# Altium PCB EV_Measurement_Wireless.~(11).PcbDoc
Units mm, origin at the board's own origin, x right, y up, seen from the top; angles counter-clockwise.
Board outline 152.4 x 101.6 mm, 4 copper layers (Top Layer, Mid-Layer 1, Mid_Layer 2, Bottom Layer), stack 0.605 mm thick; 55 components, 38 nets, 375 pads, 56 vias.
Unrouted connection lines stored in the file: 220.
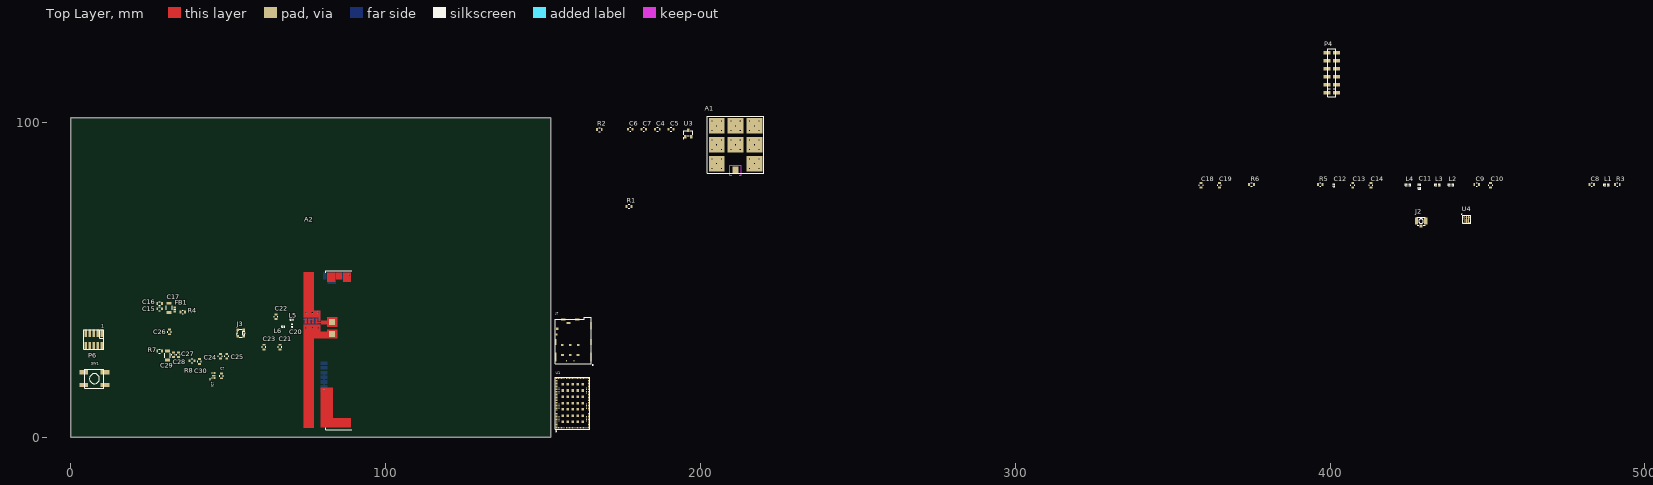
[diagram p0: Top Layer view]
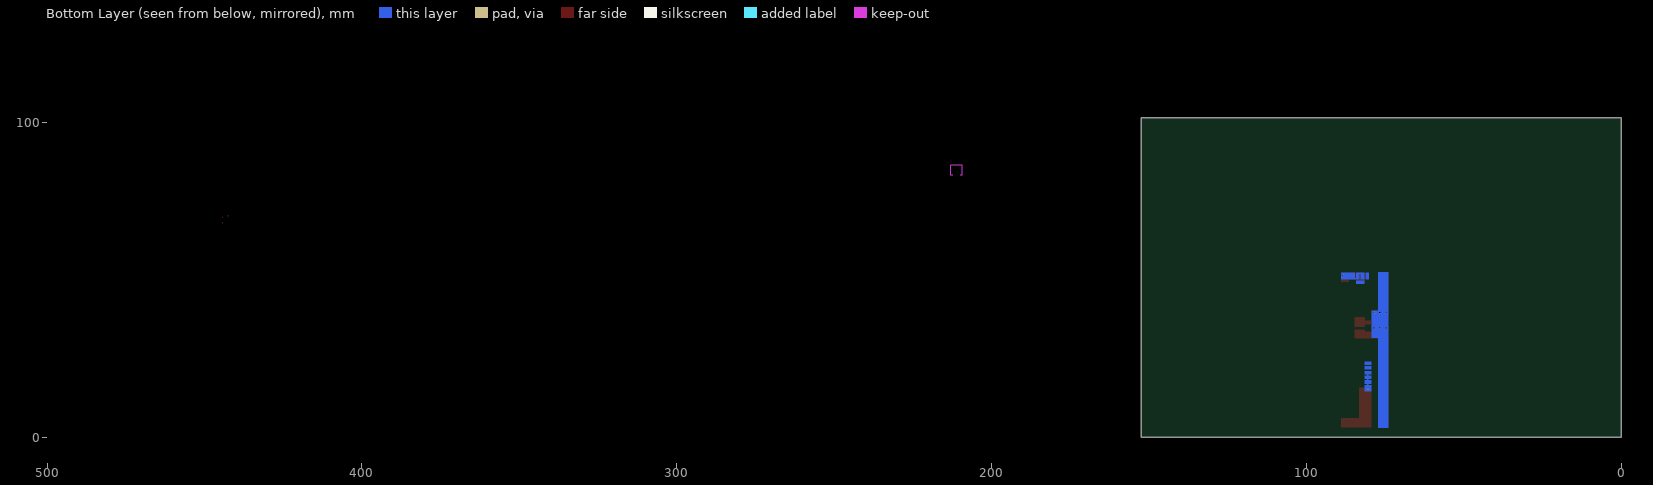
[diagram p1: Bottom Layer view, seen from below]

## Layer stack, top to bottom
Top Solder: solder mask 0.0102, Solder Resist, Dk 3.5
Top Layer: signal copper 0.0356
Dielectric 2: prepreg 0.0711, PP-006, Dk 4.1
Mid-Layer 1: signal copper 0.0356
Dielectric 1: prepreg 0.0711, PP-006, Dk 4.1
Mid_Layer 2: signal copper 0.0356
Dielectric2: dielectric 0.32, FR-4, Dk 4.1
Bottom Layer: signal copper 0.0356
Bottom Solder: solder mask 0.0102, Solder Resist, Dk 3.5

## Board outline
0,0 152.4,0 152.4,101.6 0,101.6

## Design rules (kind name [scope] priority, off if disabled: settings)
Clearance [All] p1: gap=0.254 ignorepadtopadclearanceinfootprint=FALSE
PolygonConnect [All] p1: connectstyle=Relief reliefconductorwidth=0.254 reliefentries=4 polygonreliefangle="90 Angle" airgapwidth=0.254
RoutingVias [All] p1: holewidth=0.711 width=1.27 viastyle="Through Hole" minholewidth=0.711 minwidth=1.27 maxholewidth=0.711 maxwidth=1.27
SolderMaskExpansion [All] p1: expansion=0.102 istentingtop=FALSE
SupplyNets "Schematic Supply Nets" [InNet('P0.14/AIN1')] p1: voltage=0.000
SupplyNets "Schematic Supply Nets_4" [InNet('3V3')] p2: voltage=0.000
SupplyNets "Schematic Supply Nets_3" [InNet('VDD')] p3: voltage=0.000
SupplyNets "Schematic Supply Nets_2" [InNet('VDD_nRF')] p4: voltage=0.000
Width [All] p1: maxlimit=0.254 minlimit=0.254 preferedwidth=0.254
30 further rules are at their usual default settings.

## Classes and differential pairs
net class SWD: RESET SWDCLK SWDIO
component class sheet4_sim_connections: C4 C5 C6 C7 C? IC? J? P4 P6 R1 U3
component class sheet2_nRF9160: A1 A2 C8 C9 C10 C11 C12 C13 C14 C15 C16 C17 C18 C19 C20 C21 C22 C23 C24 C25 C26 C27 C28 C29 C30 FB1 J2 J3 L1 L2 L3 L4 L5 L6 R2 R3 R4 R5 R6 R7 R8 SW1 U1 U4

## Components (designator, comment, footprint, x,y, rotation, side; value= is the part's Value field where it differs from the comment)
A1 "DSGP.1575.18" DSGP.1575.18 211.129,92.988 r0 top
A2 "P822601" P822601 85.217,27.813 r270 top
C4 "100n" 0603(1608)C 186.309,97.917 r0 top
C5 "100n" 0603(1608)C 190.627,97.917 r0 top
C6 "1u0" 0603(1608)C 177.673,97.917 r0 top
C7 "1u0" 0603(1608)C 181.991,97.917 r0 top
C8 "39p" 0603(1608)C 483.108,80.391 r0 top
C9 "39p" 0603(1608)C 446.532,80.391 r0 top
C10 "39p" 0603(1608)C 450.977,80.137 r90 top
C11 "N.C." CAPC1005X04L_NC 428.371,79.756 r90 top
C12 "N.C." CAPC0603X03L_C_NC 401.193,80.137 r90 top
C13 "100p" 0603(1608)C 407.162,80.137 r90 top
C14 "100n" 0603(1608)C 413.004,80.137 r90 top
C15 "39p" 0603(1608)C 28.194,40.894 r180 top
C16 "100n" 0603(1608)C 28.194,42.545 r180 top
C17 "47u" 1206(3216)C 31.242,41.201 r270 top
C18 "100n" 0603(1608)C 359.029,80.137 r90 top
C19 "100p" 0603(1608)C 364.871,80.137 r90 top
C20 "3.5pF" CAPC0603X03L_C 70.327,35.56 r90 top
C21 "N.C" 0603(1608)C 66.421,28.702 r90 top
C22 "N.C." 0603(1608)C 65.151,38.354 r90 top
C23 "N.C." 0603(1608)C 61.341,28.702 r90 top
C24 "100n" 0603(1608)C 47.498,25.781 r90 top
C25 "4u7" 0603(1608)C 49.53,25.781 r90 top
C26 "4u7" 0603(1608)C 31.369,33.528 r90 top
C27 "15p" 0603(1608)C 32.639,26.289 r270 top value=39p
C28 "100n" 0603(1608)C 34.163,26.289 r270 top
C29 "47u" 1206(3216)C 30.734,26.035 r270 top
C30 "100n" 0603(1608)C 40.894,24.13 r90 top
C? "100n" 0603(1608)C 47.879,19.558 r270 top
FB1 "BLM18EG221SN1D" BLM18SP221SN1B 33.02,40.68 r270 top
IC? "EMIF03SIM02M8" SON40P150X170X60-9N-D 45.412,19.647 r90 top
J2 "MHF I Receptacle" "COAXIAL RF U.FL-R-SMT-1" 428.879,68.707 r0 top
J3 "MM8130-2600" COAXIAL-SWF 53.975,33.147 r90 top
J? "SF72S006VBAR2500" SF72S006VBAR2500 165.227,23.622 r0 top
L1 "68nH" INDC1005X04L_WW 487.807,80.264 r0 top
L2 "N.C." INDC1005X04L_NC 438.404,80.264 r0 top
L3 "N.C." INDC1005X04L_NC 434.086,80.264 r0 top
L4 "9.1nH" INDC1005X04L_WW 424.688,80.264 r0 top
L5 "1.5nH" INDC0603X03L_C 70.231,37.465 r0 top
L6 "22nH" INDC0603X03L_C 67.437,35.306 r0 top
P4 "Socket 1x6" SOCKET_1x6_SMD 400.499,109.474 r90 top
P6 "Pin Header 2x5, 1.27mm" HDR_2x5-SMD-1.27mm-K 7.239,31.115 r180 top
R1 "N.C" 0603(1608) 177.292,73.406 r0 top value=0E
R2 "N.C" 0603(1608) 167.894,97.79 r0 top value=0E
R3 "0E" 0603(1608) 491.236,80.391 r0 top
R4 "10k" 0603(1608) 35.56,39.878 r0 top
R5 "0E" 0603(1608) 396.875,80.391 r0 top
R6 "1M" 0603(1608) 375.031,80.391 r0 top
R7 "N.C." 0603(1608) 28.194,27.432 r0 top value=0E
R8 "1k" 0603(1608) 38.481,24.384 r0 top
SW1 "PB SW" Switch-PB-6.2x6.3mm-SMD 7.493,18.669 r0 top
U1 "nRF9160-SICAB1A" LGA50P1600X1050X104-161N 159.385,10.922 r90 top
U3 "AP7333-33SAG-7" SOT-23A 195.199,95.504 r0 top
U4 "SKY65943-11" SKY65943-11 443.357,69.342 r0 top

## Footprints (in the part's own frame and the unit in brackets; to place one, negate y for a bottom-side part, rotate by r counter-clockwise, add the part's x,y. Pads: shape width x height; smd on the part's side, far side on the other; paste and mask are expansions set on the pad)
0603(1608) [mm] "Chip 0603 (1608 metric)"
  rect 0.6x0.9 smd: 1(-0.75,0) 2(0.75,0)
  silkscreen extent -0.2,-0.6 0.2,0.6, body extent -0.8,-0.4 0.8,0.4, height 0.3
0603(1608)C [mm] "Chip 0603 (1608 metric)"
  rect 0.6x0.9 smd: 1(-0.75,0) 2(0.75,0)
  silkscreen extent -0.2,-0.6 0.2,0.6, body extent -0.8,-0.38 0.8,0.42, height 0.5
1206(3216)C [mm] "Chip Capa 1206 (3216 metric)"
  rect 0.9x1.6 smd: 1(-1.45,0) 2(1.45,0)
  silkscreen extent -0.7,-0.9 0.7,0.9, body extent -1.6,-0.8 1.6,0.8, height 1
BLM18SP221SN1B [mm]
  rect 0.65x0.7 smd: 1(-0.675,0) 2(0.675,0)
  silkscreen extent 0,-0.3 0,0.3, body extent -0.8,-0.4 0.8,0.4, height 0.8
CAPC0603X03L_C [mm]
  rect 0.27x0.3 smd mask+0.05: 1(-0.285,0) 2(0.285,0)
  silkscreen extent -0.49,-0.22 0.49,0.22, body extent -0.3,-0.15 0.31,0.15, height 0.3
CAPC0603X03L_C_NC [mm]
  rect 0.27x0.3 smd mask+0.05: 1(-0.285,0) 2(0.285,0)
  silkscreen extent -0.49,-0.22 0.49,0.22
CAPC1005X04L_NC [mm]
  rect 0.6x0.5 smd: 1(-0.5,0) 2(0.5,0)
  silkscreen extent -0.9,-0.35 0.9,0.35
"COAXIAL RF U.FL-R-SMT-1" [mm]
  rect 1x1.05 smd: 1(0,-1.525)
  rect 1.05x2.2 smd: 2(-1.475,0) 2(1.475,0)
  Top Layer pour cut-out: 0.85,1.3 -0.85,1.3 -0.85,-1.525 0.85,-1.525
  silkscreen extent -1.32,-1.3 1.28,1.3, body extent -1.5,-1.6 1.5,1.5, height 1.25
COAXIAL-SWF [mm]
  rect 0.5x0.58 smd: 1(0,1.16) 3(0,-1.16)
  rect 0.75x0.8 smd: 2(-1.025,-0.95) 2(-1.025,0.95) 2(1.025,-0.95) 2(1.025,0.95)
  Top Layer pour cut-out: -0.65,0.55 0.65,0.55 0.65,1.35 -0.65,1.35
  Top Layer pour cut-out: 0.65,-0.55 -0.65,-0.55 -0.65,-1.35 0.65,-1.35
  silkscreen extent -1.25,-1.25 1.25,1.25, body extent -1.26,-1.3 1.26,1.3, height 1.55
DSGP.1575.18 [mm]
  rect 2x2.5 smd paste-0.25 mask+0.1: 1(0,-8.1)
  rect 5x5 smd paste-0.6 mask+0.1: 2(-6,-6) 2(-6,0) 2(-6,6) 2(0,0) 2(0,6) 2(6,-6) 2(6,0) 2(6,6)
  round 0.35 on Mech16: 11(-7.5,-7.5) 11(-7.5,-4.5) 11(-7.5,-1.5) 11(-7.5,1.5) 11(-7.5,4.5) 11(-7.5,7.5) 11(-6,-6) 11(-6,0) 11(-6,6) 11(-4.5,-7.5) 11(-4.5,-4.5) 11(-4.5,-1.5) 11(-4.5,1.5) 11(-4.5,4.5) 11(-4.5,7.5) 11(-1.5,-1.5) 11(-1.5,1.5) 11(-1.5,4.5) 11(-1.5,7.5) 11(0,0) 11(0,6) 11(1.5,-1.5) 11(1.5,1.5) 11(1.5,4.5) 11(1.5,7.5) 11(4.5,-7.5) 11(4.5,-4.5) 11(4.5,-1.5) 11(4.5,1.5) 11(4.5,4.5) 11(4.5,7.5) 11(6,-6) 11(6,0) 11(6,6) 11(7.5,-7.5) 11(7.5,-4.5) 11(7.5,-1.5) 11(7.5,1.5) 11(7.5,4.5) 11(7.5,7.5)
  Keep-Out Layer lines w0.01: -1.26,-9.69 -1.84,-9.69 -1.84,-6.51 1.84,-6.51 1.84,-9.69 1.26,-9.69
  Multi-Layer pour cut-out: -2,-6.35 -2,-9.85 2,-9.85 2,-6.35
  silkscreen extent -9,-9 9,9, body extent -9,-9 9,9, height 4.03
HDR_2x5-SMD-1.27mm-K [mm]
  rect 0.76x2.4 smd: 1(-2.54,-1.95) 2(-2.54,1.95) 3(-1.27,-1.95) 4(-1.27,1.95) 5(0,-1.95) 6(0,1.95) 7(1.27,-1.95) 8(1.27,1.95) 9(2.54,-1.95) 10(2.54,1.95)
  silkscreen extent -3.18,-3.15 3.18,3.15, body extent -3.14,-2.92 3.14,2.92, height 6.11
INDC0603X03L_C [mm]
  rect 0.27x0.3 smd: 1(-0.285,0) 2(0.285,0)
  silkscreen extent -0.49,-0.22 0.49,0.22, body extent -0.31,-0.16 0.31,0.16, height 0.26
INDC1005X04L_NC [mm]
  rect 0.65x0.5 smd: 1(-0.475,0) 2(0.475,0)
  silkscreen extent -0.9,-0.35 0.9,0.35
INDC1005X04L_WW [mm]
  rect 0.65x0.5 smd: 1(-0.475,0) 2(0.475,0)
  silkscreen extent -0.9,-0.35 0.9,0.35, body extent -0.5,-0.3 0.5,0.3, height 0.51
LGA50P1600X1050X104-161N [mm]
  rect 0.54x0.54 smd mask+0.05: 1(-7.87,5.12) 21(-7.87,-5.12) 52(7.87,-5.12) 72(7.87,5.12)
  rect 0.54x0.3 smd mask+0.05: 2(-7.87,4.5) 3(-7.87,4) 4(-7.87,3.5) 5(-7.87,3) 6(-7.87,2.5) 7(-7.87,2) 8(-7.87,1.5) 9(-7.87,1) 10(-7.87,0.5) 11(-7.87,0) 12(-7.87,-0.5) 13(-7.87,-1) 14(-7.87,-1.5) 15(-7.87,-2) 16(-7.87,-2.5) 17(-7.87,-3) 18(-7.87,-3.5) 19(-7.87,-4) 20(-7.87,-4.5) 53(7.87,-4.5) 54(7.87,-4) 55(7.87,-3.5) 56(7.87,-3) 57(7.87,-2.5) 58(7.87,-2) 59(7.87,-1.5) 60(7.87,-1) 61(7.87,-0.5) 62(7.87,0) 63(7.87,0.5) 64(7.87,1) 65(7.87,1.5) 66(7.87,2) 67(7.87,2.5) 68(7.87,3) 69(7.87,3.5) 70(7.87,4) 71(7.87,4.5)
  rect 0.3x0.54 smd mask+0.05: 22(-7.25,-5.12) 23(-6.75,-5.12) 24(-6.25,-5.12) 25(-5.75,-5.12) 26(-5.25,-5.12) 27(-4.75,-5.12) 28(-4.25,-5.12) 29(-3.75,-5.12) 30(-3.25,-5.12) 31(-2.75,-5.12) 32(-2.25,-5.12) 33(-1.75,-5.12) 34(-1.25,-5.12) 35(-0.75,-5.12) 36(-0.25,-5.12) 37(0.25,-5.12) 38(0.75,-5.12) 39(1.25,-5.12) 40(1.75,-5.12) 41(2.25,-5.12) 42(2.75,-5.12) 43(3.25,-5.12) 44(3.75,-5.12) 45(4.25,-5.12) 46(4.75,-5.12) 47(5.25,-5.12) 48(5.75,-5.12) 49(6.25,-5.12) 50(6.75,-5.12) 51(7.25,-5.12) 73(7.25,5.12) 74(6.75,5.12) 75(6.25,5.12) 76(5.75,5.12) 77(5.25,5.12) 78(4.75,5.12) 79(4.25,5.12) 80(3.75,5.12) 81(3.25,5.12) 82(2.75,5.12) 83(2.25,5.12) 84(1.75,5.12) 85(1.25,5.12) 86(0.75,5.12) 87(0.25,5.12) 88(-0.25,5.12) 89(-0.75,5.12) 90(-1.25,5.12) 91(-1.75,5.12) 92(-2.25,5.12) 93(-2.75,5.12) 94(-3.25,5.12) 95(-3.75,5.12) 96(-4.25,5.12) 97(-4.75,5.12) 98(-5.25,5.12) 99(-5.75,5.12) 100(-6.25,5.12) 101(-6.75,5.12) 102(-7.25,5.12)
  rect 0.8x0.8 smd mask+0.05: 103(-6,-3.2) 103(-6,-1.6) 103(-6,0) 103(-6,1.6) 103(-6,3.2) 103(-4,-3.2) 103(-4,-1.6) 103(-4,0) 103(-4,1.6) 103(-4,3.2) 103(-2,3.2) 103(-2,-1.6) 103(-2,0) 103(-2,1.6) 103(-2,-3.2) 103(0,3.2) 103(0,1.6) 103(0,0) 103(0,-1.6) 103(0,-3.2) 103(2,3.2) 103(2,-1.6) 103(2,0) 103(2,1.6) 103(2,-3.2) 103(4,-3.2) 103(4,-1.6) 103(4,0) 103(4,1.6) 103(4,3.2) 103(6,-3.2) 103(6,-1.6) 103(6,0) 103(6,1.6) 103(6,3.2)
  rect 0.3x0.3 smd mask+0.05: 104(-5.75,-4.35) 105(-5.25,-4.35) 106(-4.75,-4.35) 107(-4.25,-4.35) 108(-1.75,-4.35) 109(-1.25,-4.35) 110(-0.75,-4.35) 111(-0.25,-4.35) 112(3.25,-4.35) 113(3.75,-4.35) 114(4.25,-4.35) 115(4.75,-4.35) 116(4.75,4.35) 117(4.25,4.35) 118(3.75,4.35) 119(3.25,4.35) 120(-0.25,4.35) 121(-0.75,4.35) 122(-1.25,4.35) 123(-1.75,4.35) 124(-4.25,4.35) 125(-4.75,4.35) 126(-5.25,4.35) 127(-5.75,4.35)
  Top Layer pour cut-out: -8.15,5.4 8.15,5.4 8.15,-5.4 -8.15,-5.4
  silkscreen extent -9.05,-5.5 8.25,5.5, body extent -8.05,-5.3 8.05,5.3, height 1.2
P822601 [mm]
  rect 2x2 smd: 1(-8.89,-2.286) 2(-5.08,-2.286)
  Top Layer region: -8.45,-8.196 -8.95,-8.196 -8.95,-7.996 -8.45,-7.996
  Top Layer region: -9.45,-8.196 -9.95,-8.196 -9.95,-7.996 -9.45,-7.996
  Top Layer region: -8.45,-8.396 -9.95,-8.396 -9.95,-8.196 -8.45,-8.196
  Top Layer region: -8.45,-8.596 -8.95,-8.596 -8.95,-8.396 -8.45,-8.396
  Top Layer region: -9.45,-8.596 -9.95,-8.596 -9.95,-8.396 -9.45,-8.396
  Top Layer region: -9.6,-9.196 -9.8,-9.196 -9.8,-8.596 -9.6,-8.596
  Top Layer region: -8.45,-9.396 -8.95,-9.396 -8.95,-9.196 -8.45,-9.196
  Top Layer region: -9.45,-9.396 -9.95,-9.396 -9.95,-9.196 -9.45,-9.196
  Top Layer region: -8.45,-9.596 -9.95,-9.596 -9.95,-9.396 -8.45,-9.396
  Top Layer region: -8.45,-9.796 -8.95,-9.796 -8.95,-9.596 -8.45,-9.596
  Top Layer region: -9.45,-9.796 -9.95,-9.796 -9.95,-9.596 -9.45,-9.596
  Top Layer region: -21.6,1.254 -24.5,1.254 -24.5,3.754 -21.6,3.754
  Top Layer region: -22.4,-0.846 -24.5,-0.846 -24.5,0.854 -22.4,0.854
  Top Layer region: -21.6,-3.746 -24.5,-3.746 -24.5,-1.246 -21.6,-1.246
  Top Layer region: 24.6,-5.796 12.05,-5.796 12.05,-2.046 24.6,-2.046
  Top Layer region: 24.6,-2.046 21.7,-2.046 21.7,3.754 24.6,3.754
  Top Layer region: -3.67,-7.991 -8.05,-7.991 -8.05,-5.996 -3.67,-5.996
  Top Layer region: -3.67,-5.996 -5.71,-5.996 -5.71,-3.826 -3.67,-3.826
  Top Layer region: -3.67,-3.826 -6.399,-3.826 -6.4,-0.566 -3.67,-0.566
  Top Layer region: -10.45,-7.996 -12.45,-7.996 -12.45,-6.496 -10.45,-6.496
  Top Layer region: -9.2,-6.496 -12.45,-6.496 -12.45,-5.996 -9.2,-5.996
  Top Layer region: -9.45,-7.496 -9.95,-7.496 -9.95,-7.296 -9.45,-7.296
  Top Layer region: -8.45,-7.496 -8.95,-7.496 -8.95,-7.296 -8.45,-7.296
  Top Layer region: -8.45,-7.296 -9.95,-7.296 -9.95,-7.096 -8.45,-7.096
  Top Layer region: -9.45,-7.096 -9.95,-7.096 -9.95,-6.896 -9.45,-6.896
  Top Layer region: -8.45,-7.096 -8.95,-7.096 -8.95,-6.896 -8.45,-6.896
  Top Layer region: -8.6,-6.896 -8.8,-6.896 -8.8,-5.696 -8.6,-5.696
  Top Layer region: -8.2,-5.696 -9.2,-5.696 -9.2,-3.796 -8.2,-3.796
  Top Layer region: -7.3,-3.796 -10.4,-3.796 -10.4,-0.596 -7.3,-0.596
  Top Layer region: -9.6,-11.296 -9.8,-11.296 -9.8,-10.896 -9.6,-10.896
  Top Layer region: -9.45,-10.896 -9.95,-10.896 -9.95,-10.696 -9.45,-10.696
  Top Layer region: -8.45,-10.896 -8.95,-10.896 -8.95,-10.696 -8.45,-10.696
  Top Layer region: -8.45,-10.696 -9.95,-10.696 -9.95,-10.496 -8.45,-10.496
  Top Layer region: -9.45,-10.496 -9.95,-10.496 -9.95,-10.296 -9.45,-10.296
  Top Layer region: -8.45,-10.496 -8.95,-10.496 -8.95,-10.296 -8.45,-10.296
  Top Layer region: 24.75,-11.296 -8.05,-11.296 -8.05,-8.001 24.75,-8.001
  Top Layer region: -10.45,-11.296 -24.65,-11.296 -24.65,-7.996 -10.45,-7.996
  Bottom Layer region: -22.5,-3.546 -24.5,-3.546 -24.5,-2.546 -22.5,-2.546
  Bottom Layer region: -24.196,-2.546 -24.5,-2.546 -24.5,-2.046 -24.196,-2.046
  Bottom Layer region: -22.5,-2.046 -24.5,-2.046 -24.5,-1.046 -22.5,-1.046
  Bottom Layer region: -22.5,-1.046 -22.8,-1.046 -22.8,-0.546 -22.5,-0.546
  Bottom Layer region: -22.5,-0.546 -24.5,-0.546 -24.5,3.754 -22.5,3.754
  Bottom Layer region: -21,-3.546 -22,-3.546 -22,-1.046 -21,-1.046
  Bottom Layer region: -22.5,-5.046 -24.5,-5.046 -24.5,-4.046 -22.5,-4.046
  Bottom Layer region: 7.7,-5.796 6.7,-5.796 6.7,-4.896 7.7,-4.896
  Bottom Layer region: 9.2,-5.796 8.2,-5.796 8.2,-4.896 9.2,-4.896
  Bottom Layer region: 10.7,-5.796 9.7,-5.796 9.7,-4.896 10.7,-4.896
  Bottom Layer region: 13.2,-5.796 11.2,-5.796 11.2,-4.896 13.2,-4.896
  Bottom Layer region: 13.2,-4.896 6.7,-4.896 6.7,-4.596 13.2,-4.596
  Bottom Layer region: 7.7,-4.596 6.7,-4.596 6.7,-3.746 7.7,-3.746
  Bottom Layer region: 9.2,-4.596 8.2,-4.596 8.2,-3.746 9.2,-3.746
  Bottom Layer region: 10.7,-4.596 9.7,-4.596 9.7,-3.746 10.7,-3.746
  Bottom Layer region: 13.2,-4.596 11.2,-4.596 11.2,-3.746 13.2,-3.746
  Bottom Layer region: 6.2,-5.796 5.2,-5.796 5.2,-3.746 6.2,-3.746
  Bottom Layer region: 4.7,-5.796 3.7,-5.796 3.7,-3.746 4.7,-3.746
  Bottom Layer region: -3.86,-7.996 -12.45,-7.996 -12.45,-5.996 -3.86,-5.996
  Bottom Layer region: 24.752,-11.296 -24.648,-11.296 -24.65,-7.996 24.75,-7.996
  Multi-Layer pour cut-out: -39.95,5.08 39.05,5.08 39.05,-7.996 -39.95,-7.996
  silkscreen extent -25.2,-4.25 25.3,4.05, body extent -24.95,-4 25.05,4, height 3.2
SF72S006VBAR2500 [mm]
  rect 0.45x2.9 smd: 0(-11.175,1.9) 0(0,1.9)
  rect 0.45x1.9 smd: 0(-11.175,6.75) 0(0,6.75)
  rect 0.75x0.7 smd: 0(-10.675,10.9)
  rect 1.4x0.5 smd: 0(-8.78,13.85) 0(-4.38,13.85)
  rect 0.3x0.6 smd: 0(-7.8,0.75) 0(-5.36,0.75)
  rect 0.45x2.4 smd: 0(0,11.9)
  rect 0.9x0.7 smd: C1(-4.14,2.6) C2(-6.58,2.6) C3(-9.02,2.6) C5(-4.04,5.77) C6(-6.58,5.77) C7(-9.12,5.77)
  rect 0.6x0.6 smd: CSW(-10.95,9.1)
  rect 1.2x0.65 smd: DSW(-7.13,12.775)
  Top Layer pour cut-out: -10.084,9.5 -3.073,9.5 -3.073,-0.025 -10.084,-0.025
  Top Layer pour cut-out: -8.407,13.106 -3.48,13.106 -3.48,9.855 -8.407,9.855
  silkscreen extent -11.3,-0.67 0.67,14.53, body extent -11.2,0.05 0.02,14.4, height 1.25
SKY65943-11 [mm]
  rect 0.425x0.515 smd mask+0.05: 1(-1.188,1.144) 5(-1.188,-1.144) 6(1.188,-1.144) 10(1.188,1.144)
  rect 0.425x0.275 smd mask+0.05: 2(-1.188,0.5) 3(-1.188,0) 4(-1.188,-0.5) 7(1.188,-0.5) 8(1.188,0) 9(1.188,0.5)
  rect 1.45x2.802 smd paste-2 mask-5: 11(0,0)
  rect 1.55x2.487 on Top Solder: ""(0,0)
  Top Layer region: -0.988,0.887 -0.713,0.887 -0.713,1.4 -0.988,1.4
  Top Layer region: 0.712,-1.4 0.987,-1.4 0.987,-0.887 0.712,-0.887
  Top Layer region: 0.712,0.363 0.987,0.363 0.987,0.637 0.712,0.637
  Top Layer region: -0.712,-0.362 -0.987,-0.362 -0.987,-0.637 -0.712,-0.637
  silkscreen extent -1.65,-1.3 1.3,1.65, body extent -1.25,-1.25 1.25,1.25, height 0.71
SOCKET_1x6_SMD [mm]
  rect 1.02x2.19 smd: 1(0,1.465) 1(0,-1.465) 2(2.54,-1.465) 2(2.54,1.465) 3(5.08,-1.465) 3(5.08,1.465) 4(7.62,-1.465) 4(7.62,1.465) 5(10.16,-1.465) 5(10.16,1.465) 6(12.7,1.465) 6(12.7,-1.465)
  silkscreen extent -1.27,-1.27 13.97,1.27, body extent -1.27,-2.29 13.97,2.29, height 7.47
SON40P150X170X60-9N-D [mm]
  rect 0.7x0.2 smd: 1(-0.8,0.6) 2(-0.8,0.2) 3(-0.8,-0.2) 4(-0.8,-0.6) 5(0.8,-0.6) 6(0.8,-0.2) 7(0.8,0.2) 8(0.8,0.6)
  rect 0.5x1.1 smd: 9(0,0)
  silkscreen extent -1.27,1.07 -1.03,1.32, body extent -0.8,-0.85 0.8,0.85, height 0.6
SOT-23A [mil]
  rect 30x40 smd: 1(0,0) 2(74.8,0) 3(37.4,82.68)
  silkscreen extent -27,-21 94,79, body extent -20,-5 95,87, height 39
Switch-PB-6.2x6.3mm-SMD [mm]
  rect 2.75x1.4 smd: 1(-3.375,2) 1(3.375,2) 2(-3.375,-2) 2(3.375,-2)
  silkscreen extent -3,-3 3,3, body extent -4,-3 4,3.3, height 3.1

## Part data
A1: library part DSGP.1575.18.4.A.02, "18 x 18 mm Low Profile GPS L1 / GALILEO E1 Passive Patch Antenna", Manufacturer=Taoglas, Part number IPS=00000004435, Part number Norautron=N.A., Supplier Part Number 1=931-1511-1-ND
A2: "ANTENNA PRESTTA OCTABAND LTE", Manufacturer=Ethertronics, Part number IPS=00000009001, Part number Norautron=N.A.
C4 C5 C14 C16 C18 C24 C28 C30 C?: library part C0603_5_100n_25V, "Cer Chip Capacitor / 100n/ +-5%/ 25V", Capacitance=100nF, Case Code (Imperial)=0603, Case Code (Metric)=1608, Dielectric=X7R, Manufacturer 1=Yageo, Manufacturer Part Number=CC0603KRX7R8BB104, Max Operating Temperature=125°C, Min Operating Temperature=-55°C, Package Quantity=1, Special Value 1=+-5%, Special Value 2=25V, Supplier Part Number 1=311-1341-1-ND, Tolerance=10%
C6 C7: library part C0603_6_1u0_25V, "Cer Chip Capacitor / 1u0 / +-10%/ 25V", Capacitance=1uF, Case Code (Imperial)=0603, Case Code (Metric)=1608, Manufacturer 1=Samsung, Manufacturer Part Number=CL10B105KA8VPNC, Max Operating Temperature=125°C, Min Operating Temperature=-55°C, Special Value 1=+-10%, Special Value 2=25V, Supplier Part Number 1=1276-6617-1-ND, Tolerance=10%
C8 C9 C10: library part C0603_1_39p_50V, "Cer Chip Capacitor / 39p/ +-1%/ 50V", Manufacturer=Murata, Manufacturer P/N=GCM1885C1H390FA16J, Special Value 1=+-1%, Special Value 2=50V
C11: library part C0402-N.C., "Not mounted", Manufacturer=N.A.
C12: library part C0201-N.C., "Not mounted", Manufacturer=N.A.
C13 C19: library part C0603_2_100p_50V, "Cer Chip Capacitor / 100p/ +-1%/ 50V", Manufacturer=Murata, Manufacturer P/N=GCM1885C1H101FA16D, Special Value 1=+-1%, Special Value 2=50V
C15 C27: library part C0603_1_39p_50V, "Cer Chip Capacitor / 15p/ +-1%/ 50V", Manufacturer=Murata, Manufacturer P/N=GCM1885C1H390FA16J, Special Value 1=+-1%, Special Value 2=50V
C17 C29: library part C1206_7_47u_6.3V, "Cer Chip Capacitor / 47u/ +-10%/ 6.3V", Capacitance=47uF, Case Code (Imperial)=1206, Case Code (Metric)=3216, Dielectric=X5R, Manufacturer 1=Samsung, Manufacturer Part Number=CL31A476MQHNNNE, Max Operating Temperature=85°C, Min Operating Temperature=-55°C, Package Quantity=1, Special Value 1=+-20%, Special Value 2=6.3V, Supplier Part Number 1=1276-1167-1-ND, Tolerance=20%
C20: library part C0201-3.5p, "Capacitor, NP0, ±0.1pF, 25V", Manufacturer=Murata, Manufacturer Part Number=GJM0335C1H3R5BB01E, Part number IPS=00000001469, Part number Norautron=N.A.
C21 C22 C23: library part C0603, "Cer Chip Capacitor"
C25 C26: library part C0603_6_4u7_25V, "Cer Chip Capacitor / 4u7/ +-10%/ 25V", Capacitance=4.7uF, Case Code (Imperial)=0603, Case Code (Metric)=1608, Dielectric=X5R, Manufacturer 1=Samsung, Manufacturer Part Number=CL10A475MA8NQNC, Max Operating Temperature=85°C, Min Operating Temperature=-55°C, Package Quantity=1, Special Value 1=+-10%, Special Value 2=25V, Supplier Part Number 1=1276-1903-1-ND, Tolerance=20%
FB1: "Ferrite Bead", Manufacturer_Name="Murata Electronics", Mouser Part Number=81-BLM18EG221SN1D
IC?: "Integrated Circuit", Manufacturer_Name=STMicroelectronics
J2: library part 20279-001E-03, "Ultraminiature Coaxial Connector, 50 Ohm, SMD", Manufacturer=Wellshow, Part number IPS=00000004436, Part number Norautron=N.A.
J3: "Coaxial Connector with Switch", Manufacturer=Murata, Part number IPS=00000009955, Part number Norautron=N.A., Supplier Part Number 1=490-4981-1-ND
J?: "n 8 (6 + 2) Position Card Connector NANO SIM Surface Mount, Right Angle Gold", Manufacturer="JAE Electronics", Part number IPS=00000009956, Part number Norautron=N.A., Supplier Part Number 1=670-2799-1-ND
L1: library part L0402-68n-Wirewound-Murata, "Inductor, 140mA, ±2%, 1960mΩ, Q=20", Manufacturer=Murata, Manufacturer Part Number=LQW15AN68NG00, Part number IPS=00000002494, Part number Norautron=N.A., Supplier Part Number 1=490-6837-1-ND
L2 L3: library part L0402-N.C., "Not mounted", Manufacturer=N.A.
L4: library part L0402-9n1-Wirewound-Murata, "Inductor, 540mA, ±2%, 140mΩ, Q=25", Manufacturer=Murata, Manufacturer Part Number=LQW15AN9N1G00, Part number IPS=00000002497, Part number Norautron=N.A., Supplier Part Number 1=490-6854-1-ND
L5: library part L0201-1n5, "Inductor, 650mA, ±0.1nH", Manufacturer=Murata, Manufacturer Part Number=LQP03TQ1N5B02D, Part number IPS=00000000836, Part number Norautron=N.A.
L6: library part L0201-22n, "Chip Inductor", Manufacturer=N.A., Part number IPS=00000001478
P4: library part "Socket 1x6 SMD", "Socket 1x6, 2.54mm (100mil), SMD", Manufacturer=W-CON, Manufacturer Part Number=2171-106MS0CUNR1, Part number IPS=00000009964, Part number Norautron=N.A.
P6: library part "Pin Header 2x5 SMD, 1.27mm, KS", "Pin Header 2x5, 1.27mm (50mil), SMD, Keying Shroud", Manufacturer=W-CON, Manufacturer Part Number=3132-10MS0BK00R1, Part number IPS=00000009968, Part number Norautron=N.A.
R1 R2 R3 R5 R7: library part R0603_0_0E, "Chip Resistor / 0E / 1% / 50V / 100mW / 0603(1608)", Case Code (Imperial)=0603, Case Code (Metric)=1608, Manufacturer 1=Panasonic, Manufacturer Part Number=ERJ-3GEY0R00V, Max Operating Temperature=155°C, Max Power Dissipation=100mW, Min Operating Temperature=-55°C, Package Quantity=1, Resistance=0mR, Special Value 1=1%, Special Value 2=50V, Supplier Part Number 1=311-0.0HRCT-ND, Temperature Coefficient=600ppm/°C, Tolerance=0%, Voltage Rating=75V
R4: library part R0603_4_10k, "Chip Resistor / 10k/ 1% / 50V / 100mW / 0603(1608)", Case Code (Imperial)=0603, Case Code (Metric)=1608, Manufacturer 1=Susumu, Manufacturer Part Number=RR0816P-103-D, Max Operating Temperature=125°C, Max Power Dissipation=63mW, Min Operating Temperature=-55°C, Package Quantity=1, Resistance=10kR, Special Value 1=1%, Special Value 2=50V, Special Value 3=100mW, Supplier Part Number 1=RR08P10.0KDCT-ND, Temperature Coefficient=25ppm/°C, Tolerance=0.5%, Voltage Rating=75V
R6: library part R0603_6_1M, "Chip Resistor / 1M/ 1% / 50V / 100mW / 0603(1608)", Case Code (Imperial)=1206, Case Code (Metric)=3216, Manufacturer Part Number=ERJ-8ENF1004V, Max Operating Temperature=155°C, Max Power Dissipation=250mW, Min Operating Temperature=-55°C, Package Quantity=1, Resistance=1MR, Special Value 1=1%, Special Value 2=50V, Special Value 3=100mW, Supplier Part Number 1=311-1.00MHRCT-ND, Temperature Coefficient=100ppm/°C, Voltage Rating=200V
R8: library part R0603_3_1k, "Chip Resistor / 1k/ 1% / 50V / 100mW / 0603(1608)", Case Code (Imperial)=1206, Case Code (Metric)=3216, Manufacturer=Panasonic, Manufacturer Part Number=ERA-8AEB102V, Max Operating Temperature=155°C, Max Power Dissipation=250mW, Min Operating Temperature=-55°C, Package Quantity=5000, Resistance=1kR, Special Value 1=1%, Special Value 2=50V, Special Value 3=100mW, Supplier Part Number 1=P1.0KDBCT-ND, Temperature Coefficient=25ppm/°C, Tolerance=0.1%, Voltage Rating=150V
SW1: library part Switch-PB-6.2x6.3mm-SMD, "Tactile Switch, SPNO, SMD, 160gf, 6.2x6.3x2.5mm", Manufacturer=Dailywell, Manufacturer Part Number=TS604VM1-025BR-R, Part number IPS=00000007812, Part number Norautron=N.A.
U1: "Low power System-in-Package with integrated LTE-M/NB-IoT modem and GPS", Manufacturer="Nordic Semiconductor", Part number IPS=80000002329, Part number Norautron=N.A.
U3: "300mA, Low Quiescent Current, Fast Transient Low Dropout Linear Regulator", Manufacturer="Diodes Incorporated", Part number IPS=00000001673, Part number Norautron=N.A., Supplier Part Number 1=AP7333-33SAG-7DICT-ND
U4: "GNSS Low-Noise Amplifier Front-End Module with Integrated Pre-Filter and Post-Filter", Manufacturer=Skyworks, Part number IPS=00000002997, Part number Norautron=N.A., Supplier Part Number 1=863-2032-1-ND

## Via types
v1: diameter 0.35, hole 0.15, Top Layer to Mid-Layer 1, 48 vias
v2: diameter 0.5, hole 0.25, Top Layer to Bottom Layer, 8 vias

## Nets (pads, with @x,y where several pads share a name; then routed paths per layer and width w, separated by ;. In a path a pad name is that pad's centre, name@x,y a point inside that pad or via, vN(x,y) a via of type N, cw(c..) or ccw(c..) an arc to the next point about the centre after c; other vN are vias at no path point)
3V3: C7.1 C8.2 L1.1 U3.2
ANT: C21.2 J3.3 L5.1
DEC0: C26.1 U1.13
GPS_EN: R5.1 R6.2 U1.93
GPS_RF1: C9.2 U1.67
GPS_RF2: C9.1 C10.2 J2.1 L1.2 L2.1
GPS_RF3: C10.1 U4.10
GPS_RF4: L3.1 R3.1 U4.5
GPS_RF7: A1.1 C11.1 R3.2
LTE_RF1: J3.1 U1.61 | length 0.1
  Top Layer w0.254: J3.1@52.736,33.068 J3.1
NetA2_1: A2.1 C20.2 L6.2
NetC12_2: C12.2 L2.2
NetC13_2: C13.2 C14.2 R2.1 U4.3
NetC18_2: C18.2 C19.2 R5.2 U4.2
NetC20_1: C20.1 C22.2 C23.2 L5.2
NetC27_1: C27.1 C28.1 C29.1 R7.2 U1.22
NetC30_1: C30.1 R8.2 U1.32
NetFB1_2: FB1.2 R4.1 U1.102
NetIC?_5: IC?.5 J?.C7
NetIC?_6: IC?.6 J?.C3
NetIC?_7: IC?.7 J?.C2
NetL4_1: L4.1 U4.8
NetL4_2: L4.2 U4.7
NetR4_2: R4.2 U1.101
P0.14/AIN1: A1.2 A2.2 C4.2 C5.1 C6.2 C7.2 C8.1 C11.2 C12.1 C13.1 C14.1 C15.2 C16.2 C17.2 C18.1 C19.1 C21.1 C22.1 C23.1 C24.2 C25.2 C26.2 C27.2 C28.2 C29.2 C30.2 C?.1 IC?.9 J2.2 J3.2 J?.0 J?.C5 L3.2 L6.1 P4.1 P4.2 P4.3 P4.4 P4.5 P4.6 P6.3 P6.5 P6.9 R6.1 SW1.1 U1.1 U1.5 U1.6 U1.7 U1.8 U1.9 U1.11 U1.14 U1.17 U1.21 U1.24 U1.27 U1.31 U1.36 U1.41 U1.44 U1.47 U1.50 U1.52 U1.56 U1.60 U1.62 U1.63 U1.65 U1.66 U1.68 U1.69 U1.72 U1.74 U1.75 U1.76 U1.77 U1.78 U1.79 U1.80 U1.81 U1.82 U1.85 U1.90 U1.94 U1.98 U1.103 U3.3 U4.1 U4.4 U4.6 U4.9 U4.11
  other v1: 443.057,68.442 443.657,68.442 443.057,69.042 443.657,69.042 443.057,69.642 443.657,69.642 443.057,70.242 443.657,70.242 203.629,85.488 206.629,85.488 215.629,85.488 218.629,85.488 205.129,86.988 217.129,86.988 203.629,88.488 206.629,88.488 215.629,88.488 218.629,88.488 203.629,91.488 206.629,91.488 209.629,91.488 212.629,91.488 215.629,91.488 218.629,91.488 205.129,92.988 211.129,92.988 217.129,92.988 203.629,94.488 206.629,94.488 209.629,94.488 212.629,94.488 215.629,94.488 218.629,94.488 203.629,97.488 206.629,97.488 209.629,97.488 212.629,97.488 215.629,97.488 218.629,97.488 205.129,98.988 211.129,98.988 217.129,98.988 203.629,100.488 206.629,100.488 209.629,100.488 212.629,100.488 215.629,100.488 218.629,100.488
  other v2: 74.751,34.863 76.667,34.863 78.471,34.863 74.751,39.653 76.667,39.653 78.471,39.699
P0.15/AIN2: U1.25
P0.16/AIN3: U1.26
P0.17/AIN4: U1.28
P0.18/AIN5: U1.29
RESET: P6.10 R8.1 SW1.2
SIM_1V8: C?.2 IC?.1 IC?.8 J?.C1 U1.49
SIM_CLK: IC?.3 U1.46
SIM_IO: IC?.4 U1.48
SIM_RST: IC?.2 U1.43
SWDCLK: P6.4 U1.33
SWDIO: P6.2 U1.34
VDD: C4.1 C5.2 C6.1 C24.1 C25.1 P6.1 R1.2 R2.2 U1.12 U3.1
VDD_nRF: C15.1 C16.1 C17.1 FB1.1 R1.1 R7.1
pads on no net: A1.11 J?.C6 J?.CSW J?.DSW P6.6 P6.7 P6.8 U1.2 U1.3 U1.4 U1.10 U1.15 U1.16 U1.18 U1.19 U1.20 U1.23 U1.30 U1.35 U1.37 U1.38 U1.39 U1.40 U1.42 U1.45 U1.51 U1.53 U1.54 U1.55 U1.57 U1.58 U1.59 U1.64 U1.70 U1.71 U1.73 U1.83 U1.84 U1.86 U1.87 U1.88 U1.89 U1.91 U1.92 U1.95 U1.96 U1.97 U1.99 U1.100 U1.104 U1.105 U1.106 U1.107 U1.108 U1.109 U1.110 U1.111 U1.112 U1.113 U1.114 U1.115 U1.116 U1.117 U1.118 U1.119 U1.120 U1.121 U1.122 U1.123 U1.124 U1.125 U1.126 U1.127 U4.
copper on no net:
  other v2: 80.421,15.113 88.471,51.663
